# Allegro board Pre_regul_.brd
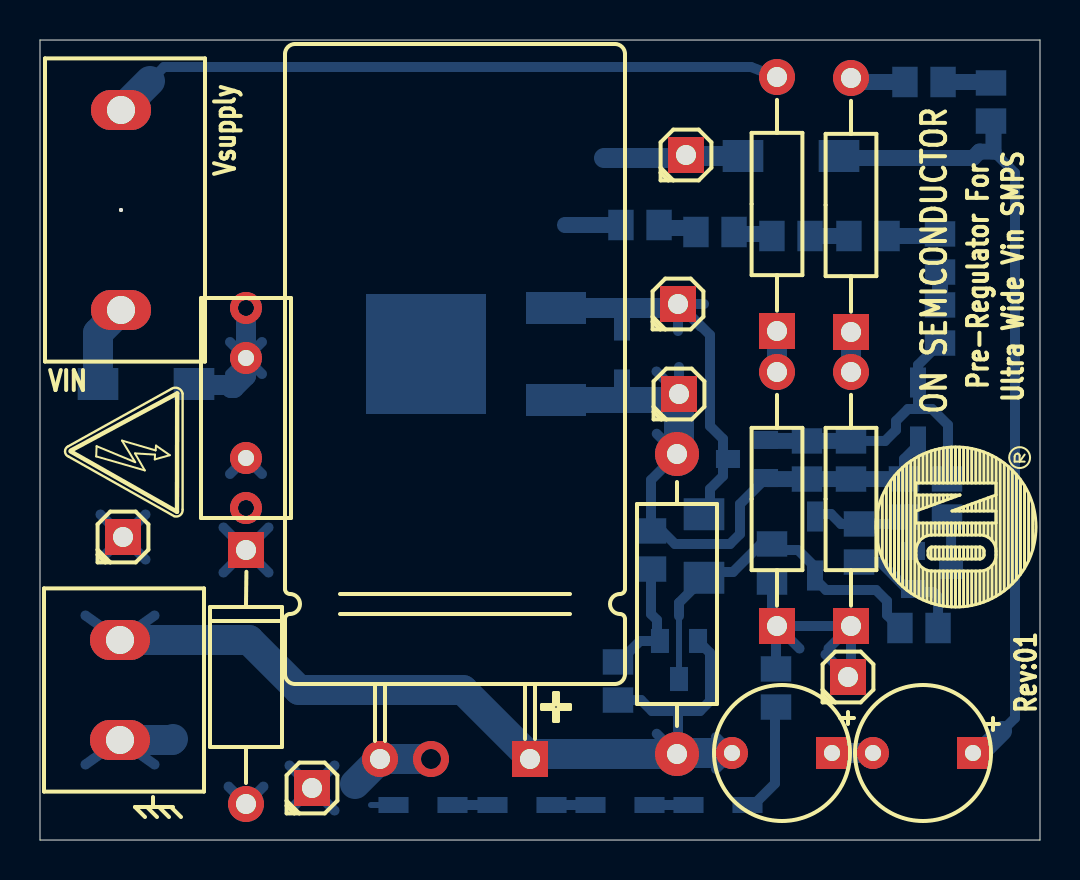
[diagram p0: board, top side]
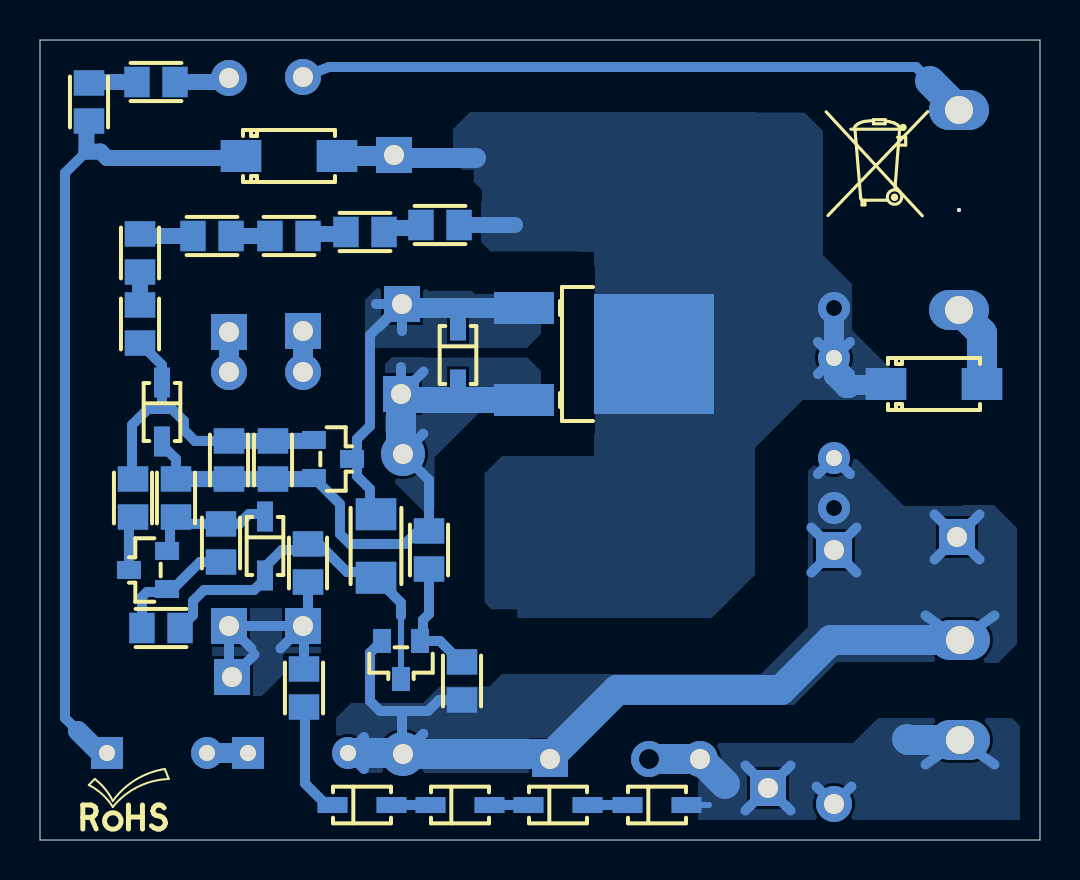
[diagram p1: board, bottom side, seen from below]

Outline 50 x 40 mm; copper layers: TOP, IN1, IN2, BOTTOM. Coordinates in mm from the lower left corner of the outline.
Outline path: 0,40 0,0 50,0 50,40 0,40

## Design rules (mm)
net group 700V: nets N2500670 V IN
net group 200-400V: nets N2499892 N2499948 N2500024 N2500332 N2500480 N2500674 N2500806 N2500814 N2500818 N2500822 N25000601
net group 600V: nets V SUPPLY

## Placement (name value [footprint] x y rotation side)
C1  100pF  [CAPA_DISK_D7-5_P5]  10.3 21.6 270 top
C2  1n  [0805]  38.35 19 90 bottom
C3  22uF 250V  [CAPA_CH_D16XL32_P5]  20.75 4.05 90 top
C4  100n  [0805]  43.2 17.1 90 bottom
C5  1 uF / 450 V  [CAPA_CH_D6-3XL11_P5]  44.15 4.35 180 top
C6  2 x 1 uF / 450 V  [CAPA_CH_D6-3XL11_P5]  37.1 4.35 180 top
CN1  CON3  [BORNIER_3P_5MM]  4.05 34 90 top
CN2  CON2  [BORNIER_2P_5MM]  4 7.5 90 top
D1  MRA4007T3G  [DO214AC_SMA_POL]  5.3 22.8 180 bottom
D2  MMSD4148  [SOD123]  43.9 21.4 270 bottom
D3  MRA4007T3G  [DO214AC_SMA_POL]  37.55 34.2 180 bottom
D4  MMSD4148  [SOD123]  38.75 14.7 270 bottom
DRAIN  TEST POINT  [HE14_1X1]  32.3 34.25 0 top
GATE  TEST POINT  [HE14_1X1]  31.9 26.8 0 top
GND  TEST POINT  [HE14_1X1]  13.6 2.6 0 top
JP1  0R  [1206]  33.2 14.7 90 bottom
NOREF  -  []  0 0 90 top
NOREF#2  -  []  0 40 0 top
NOREF#3  -  []  4.05 36.5 90 top
NOREF#4  -  []  0 40 0 top
NOREF#5  -  []  -181 -35.85 0 top
NOREF#6  -  []  -114.15 -45.45 0 top
NOREF#7  -  []  283.55 -61.75 180 bottom
Q1  NDD02N60Z  [DPAK_TO252]  20.9 24.3 270 bottom
Q2  BC848B  [SOT23]  35.35 19.05 90 bottom
Q3  BC858B  [SOT23]  44.6 13.5 270 bottom
Q4  BC848B  [SOT23]  31.95 9 180 bottom
R1  0.15 R 2W  [WP2S_15MM]  31.85 11.8 270 top
R2  10k  [0805]  40.55 19 270 bottom
R3  1k  [0805]  30.55 14.5 90 bottom
R4  NC  [0805]  28.9 7.95 90 bottom
R5  150K  [0805]  30 30.75 0 bottom
R6  150K  [0805]  33.75 30.4 180 bottom
R7  150K  [0805]  37.55 30.2 0 bottom
R8  150K  [0805]  41.4 30.2 180 bottom
R9  150K  [0805]  45 29.35 270 bottom
R10  150K  [0805]  45 25.8 270 bottom
R11  1k  [0805]  45.35 17.1 90 bottom
R12  10k  [0805]  43.95 10.6 0 bottom
R13  10k  [0805]  40.95 14.85 270 bottom
R14  10k  [0805]  36.6 13.85 90 bottom
R15  100K 1/4W  [RC21U_12-5MM]  36.85 31.8 90 top
R16  100K 1/4W  [RC21U_12-5MM]  36.85 17.05 90 top
R17  330K  [0805]  47.55 36.9 270 bottom
R18  330K  [0805]  44.2 37.9 0 bottom
R19  680K 1/4W  [RC21U_12-5MM]  40.55 31.75 90 top
R20  680K 1/4W  [RC21U_12-5MM]  40.55 17.05 90 top
R21  10k  [0805]  36.8 7.6 90 bottom
SOURCE  TEST POINT  [HE14_1X1]  31.95 22.3 0 top
VOUT  TEST POINT  [HE14_1X1]  4.15 15.15 0 top
VREF  TEST POINT  [HE14_1X1]  40.4 8.15 0 top
ZD1  10V  [SOD123]  29.1 24.25 270 bottom
ZD2  250 V  [DO15_12-5MM]  10.3 8.15 270 top
ZD3  82 V  [SOD123]  33.9 1.75 180 bottom
ZD4  82 V  [SOD123]  29 1.75 180 bottom
ZD5  110 V  [SOD123]  24.1 1.75 180 bottom
ZD6  110 V  [SOD123]  19.15 1.75 180 bottom

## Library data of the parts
C1 = C.MPP_MEF_Pitch-20mm
C2 C4 = C
C3 C5 C6 = C_elect
CN1 = CON3
CN2 = CON2
D1 D3 = D1N4937_1
D2 D4 = D1N4937_0
DRAIN GATE GND SOURCE VOUT VREF = TEST POINT_0
JP1 = JUMPER1_3
Q1 = ST723/PF_0
Q2 Q4 = BC848A
Q3 = BC858A
R1-R21 = R
ZD1-ZD6 = zener_0

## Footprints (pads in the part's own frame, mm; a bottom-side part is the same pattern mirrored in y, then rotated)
0805
  rect 1.27x1.524 smd: 1(-0.953,0) 2(0.953,0)
1206
  rect 1.6x2.03 smd: 1(-1.587,0) 2(1.587,0)
BORNIER_2P_5MM
  oval 2x3 hole 1.4: 1(2.5,0) 2(-2.5,0)
BORNIER_3P_5MM
  round 0.2 hole 1.3 unplated: (-2.5,0)
  oval 2x3 hole 1.4: 1(2.5,0) 3(-7.5,0)
CAPA_CH_D6-3XL11_P5
  round 1.6 hole 0.8: N(2.5,0)
  rect 1.6x1.6 hole 0.8: P(-2.5,0)
CAPA_CH_D16XL32_P5
  round 1.8 hole 1: N(0,3.75)
  rect 1.8x1.8 hole 1: P(0,-3.75)
CAPA_DISK_D7-5_P5
  round 1.6 hole 0.8: 1(-2.5,0) 2(2.5,0)
DO15_12-5MM
  rect 1.8x1.8 hole 1: 1(-6.35,0)
  round 1.8 hole 1: 2(6.35,0)
DO214AC_SMA_POL
  rect 2.03x1.6 smd: 1(2.4,0) 2(-2.4,0)
DPAK_TO252
  rect 1.6x3 smd: 1(-2.3,-4.9) 3(2.3,-4.9)
  rect 6x6 smd: 4(0,1.6)
HE14_1X1
  rect 1.8x1.8 hole 1: 1(0,0)
RC21U_12-5MM
  rect 1.8x1.8 hole 1: 1(-6.35,0)
  round 1.8 hole 1: 2(6.35,0)
SOD123
  rect 1.5x0.8 smd: 1(-1.475,0) 2(1.475,0)
SOT23
  rect 0.9x1.2 smd: 1(0.953,0.953) 2(-0.953,0.953) 3(0,-0.953)
WP2S_15MM
  round 2.2 hole 1: 1(-7.5,0) 2(7.5,0)

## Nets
GND: C3.N(-) CN2.2 GND.1 ZD2.2(ANODE) ZD6.2(ANODE)
V IN: CN1.3 D1.1(A)
V SUPPLY: CN1.1 R15.2
V_OUT: C1.2 C3.P(+) C6.N(-) CN2.1 Q4.2(E) R1.2 R4.1 VOUT.1 ZD2.1(CATHODE)
N2499892: R15.1 R16.2
N2499896: C1.1 D1.2(K) D3.1(A) DRAIN.1 Q1.4(D) R5.1
N2499948: C2.2 D2.1(K) Q2.1(B) R2.1 R10.2 R11.2
N2500020: C2.1 C4.2 D2.2(A) Q1.3(S) Q2.2(E) R1.1 R2.2 R3.2 SOURCE.1 ZD1.2(ANODE)
N2500024: Q3.1(B) R12.2 R13.2
N2500332: C4.1 D4.1(K) Q3.2(E) R13.1
N2500376: GATE.1 JP1.2 Q1.1(G) Q2.3(C) ZD1.1(CATHODE)
N2500480: Q4.1(B) R3.1 R4.2
N2500568: R14.1 R16.1 R20.1 R21.2 VREF.1
N2500670: C5.P(+) D3.2(K) R17.2
N2500674: C5.N(-) C6.P(+)
N2500806: ZD5.2(ANODE) ZD6.1(CATHODE)
N2500814: R21.1 ZD3.1(CATHODE)
N2500818: ZD3.2(ANODE) ZD4.1(CATHODE)
N2500822: ZD4.2(ANODE) ZD5.1(CATHODE)
N2500826: D4.2(A) JP1.1 Q4.3(C) R12.1 R14.2
N2507925: R19.1 R20.2
N2523480: R8.1 R9.1
N2523484: R7.2 R8.2
N2523488: R6.1 R7.1
N2524728: R18.1 R19.2
N25000601: Q3.3(C) R11.1
N25006620: R5.2 R6.2
N25006901: R17.1 R18.2
N25232911: R9.2 R10.1

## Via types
v1: diameter 1.6, hole 0.8, TOP to BOTTOM, 2 vias
v2: diameter 1.8, hole 1, TOP to BOTTOM, 1 via

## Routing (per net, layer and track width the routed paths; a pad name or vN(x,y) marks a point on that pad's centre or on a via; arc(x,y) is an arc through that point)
GND: length 21.2
  BOTTOM w0.3: 17.68,1.75 16.55,1.75
  BOTTOM w0.5: 9.43,2.67 ZD2.2 11.17,2.67 ; 12.47,3.73 GND.1 ; GND.1 14.73,3.73 ; GND.1 12.47,1.47 ; GND.1 14.73,1.47 ; 5.73,3.77 CN2.2 2.27,3.77
  BOTTOM w1.5: 15.75,2.8 C3.N v2(19.55,4.05) ; CN2.2 6.6,5 6.65,5.05
V IN: length 4.2
  BOTTOM w1.5: D1.1 2.9,25.35 CN1.3
V SUPPLY: length 33.8
  BOTTOM w0.5: 5.5,37.95 6.2,38.65 35.55,38.65 R15.2
  BOTTOM w1.5: CN1.1 5.5,37.95
V_OUT: length 68.1
  BOTTOM w0.5: VOUT.1 5.28,14.02 ; VOUT.1 3.02,14.02 ; VOUT.1 5.28,16.28 ; VOUT.1 3.02,16.28 ; 31.9,4.35 31.9,6.45 ; 31.9,6.45 33,6.45 33.5,6.95 33.5,9.36 Q4.2 ; 31.9,6.45 30.6,6.45 30.05,7 R4.1 ; ZD2.1 11.43,15.63 ; ZD2.1 9.17,13.37 ; ZD2.1 11.43,13.37 ; ZD2.1 9.17,15.63 ; 30.84,5.31 R1.2 ; 9.5,18.3 C1.2 11.1,18.3 ; 23.37,5.18 C3.P ; 33.8,5.15 C6.N 33.8,3.55 ; 2.27,11.23 CN2.1 5.73,11.23
  BOTTOM w1.5: C6.N 31.9,4.35 R1.2 24.75,4.3 C3.P 24.5,4.15 21.15,7.5 12.95,7.5 10.45,10 CN2.1
  vias: v1(10.3,16.6)
N2499892: length 2.1
  BOTTOM w1: R15.1 R16.2
N2499896: length 20.9
  BOTTOM w0.5: C1.1 11.1,23.3 ; C1.1 11.1,24.9 ; C1.1 9.5,23.3 ; C1.1 9.5,24.9 ; 26.15,30.85 26.25,30.75
  BOTTOM w0.8: 26.25,30.75 R5.1
  BOTTOM w1: D1.2 7.65,22.75 9.4,22.75 9.55,22.6 9.7,22.6 10.3,23.2 C1.1 v1(10.3,26.6) ; 28.2,34.1 32.15,34.1 DRAIN.1 32.35,34.2 D3.1
N2499948: length 16.8
  BOTTOM w0.5: 43.9,21.55 D2.1 43.9,23.75 R10.2 ; 43.9,21.55 43.4,21.55 42.8,20.95 42.8,20.5 42.25,19.95 R2.1 ; 43.9,21.55 44.6,21.55 45.4,20.75 45.4,18.1 R11.2
  BOTTOM w0.8: Q2.1 36.35,19.95 C2.2 R2.1
N2500020: length 36.2
  BOTTOM w0.3: ZD1.2 29.1,22
  BOTTOM w0.5: 31.95,23.65 SOURCE.1 30.82,23.43 ; Q2.2 35,16.8 35,15.3 34.5,14.8 31.75,14.8 31.1,15.45 R3.2 30.55,18 R1.1 30.84,20.31 ; C4.2 43.2,19.05 43.9,19.75 D2.2
  BOTTOM w0.8: C4.2 43.2,18.05 R2.2 C2.1 36.35,18.05 Q2.2
  BOTTOM w1.3: Q1.3 31.65,22 SOURCE.1
  BOTTOM w1.5: R1.1 31.95,19.4 SOURCE.1
N2500024: length 6.2
  BOTTOM w0.5: R12.2 44.9,12.15 44.65,12.4 43.8,12.4 Q3.1 43.35,12.55 42,13.9 R13.2
N2500332: length 6.7
  BOTTOM w0.5: Q3.2 43.5,14.6 43.5,15.85 C4.1 42.85,15.8 R13.1 40.05,15.8 39.55,16.3 38.88,16.3 D4.1
N2500376: length 23.6
  BOTTOM w0.3: 34.15,19.05 Q2.3
  BOTTOM w0.5: 29.1,25.52 ZD1.1 29.1,26.5 ; JP1.2 33.5,16.59 33.5,17.55 34.15,18.2 34.15,20.05 33.5,20.7 33.5,25.25 31.95,26.8 ; GATE.1 33.03,25.67 ; GATE.1 31.9,25.45 ; GATE.1 31.95,26.8 ; 31.95,26.8 33.2,26.8
  BOTTOM w1: 29,26.6 Q1.1 ; 29,26.6 29.1,26.5 ; 29,26.6 31.7,26.6 GATE.1
N2500480: length 6.3
  BOTTOM w0.5: R3.1 30.55,11.3 30.85,11 30.85,10.1 Q4.1 31,9.95 30,9.95 28.95,8.9 R4.2
N2500568: length 15.6
  BOTTOM w0.5: R21.2 36.8,10.65 R16.1 ; R20.1 40.55,8.3 VREF.1 39.27,9.28 ; R20.1 R16.1 ; R20.1 39.42,9.57 ; R16.1 37.98,9.57 ; R16.1 36.6,10.95 R14.1
N2500670: length 41.1
  BOTTOM w0.5: 47.68,34.42 48.75,33.35 48.75,6.1 48.1,5.45
  BOTTOM w0.8: R17.2 47.68,35.82 47.68,34.42 46.97,34.42 46.65,34.1 40.05,34.1 D3.2
  BOTTOM w1: 48.1,5.45 47,4.35 C5.P
N2500674: length 2
  BOTTOM w1: C5.N C6.P
N2500806: length 2
  BOTTOM w0.5: ZD5.2 ZD6.1
N2500814: length 5.7
  BOTTOM w0.3: ZD3.1 35.67,1.75
  BOTTOM w0.5: 35.67,1.75 36.75,2.83 36.75,6.6 R21.1
N2500818: length 1.9
  BOTTOM w0.3: ZD4.1 30.88,1.75
  BOTTOM w0.5: 30.88,1.75 ZD3.2
N2500822: length 1.9
  BOTTOM w0.5: ZD5.1 ZD4.2
N2500826: length 18.6
  BOTTOM w0.3: 31.95,11.2 Q4.3
  BOTTOM w0.5: 31.95,11.2 31.95,11.86 JP1.1 33.49,13.4 34.65,13.4 36.05,14.8 R14.2 36.9,14.5 37.9,14.5 38.75,13.65 D4.2 38.75,13.05 39.3,12.5 41.8,12.5 42.35,11.95 42.35,11.25 R12.1
N2507925: length 2.1
  BOTTOM w0.3: R20.2 40.55,23.3
  BOTTOM w1: R19.1 R20.2
N2523480: length 2.7
  BOTTOM w0.8: R8.1 44.9,30.2 R9.1
N2523484: length 1.9
  BOTTOM w0.8: R7.2 R8.2
N2523488: length 2
  BOTTOM w0.8: R6.1 34.8,30.3 36.5,30.3 R7.1
N2524728: length 2.8
  BOTTOM w0.8: R18.1 40.75,37.9 R19.2
N25000601: length 2.7
  BOTTOM w0.5: R11.1 45.55,15.95 Q3.3
N25006620: length 2
  BOTTOM w0.8: R6.2 32.6,30.6 31.1,30.6 R5.2
N25006901: length 2.4
  BOTTOM w0.8: R18.2 47.5,37.9 R17.1
N25232911: length 1.6
  BOTTOM w0.8: R9.2 R10.1

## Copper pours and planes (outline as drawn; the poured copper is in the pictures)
GND on BOTTOM: 1,1 1,5.7 1.4,6.1 8.1,6.1 9.35,4.85 17.2,4.85 17.65,4.4 17.65,3.45 17.1,2.9 17.1,1
V_OUT on BOTTOM: 3.6,8.9 10.15,8.9 12.3,6.75 20.85,6.75 24.25,3.35 34.35,3.35 35.2,4.2 35.2,6.1 34.45,6.85 30.85,6.85 30.02,7.67 27.52,7.67 26.9,8.3 13.95,8.3 11.6,10.65 11.6,18.45 10.9,19.15 9.25,19.15 6.8,16.7 3.9,16.7 3.85,16.75 2.3,16.75 1.15,15.6 1.15,9.8 2.1,8.85 3.55,8.85
N2499896 on BOTTOM: 14.25,19.6 14.25,13.25 16.4,11.1 26.25,11.1 26.62,11.47 27.38,11.47 27.77,11.88 27.77,18.32 26.88,19.23 23.35,19.23 22.25,20.32 22.25,28.68 23,29.43 27.48,29.43 27.95,29.9 27.95,31.9 27.9,31.95 27.9,32.5 29.35,33.95 29.35,35.55 28.3,36.6 14.35,36.6 14.12,36.38 11.78,36.38 10.85,35.45 10.85,29.25 9.4,27.8 9.4,25.5 7.2,23.3 7.2,22.45 7.65,22 11.85,22
N2500020 on BOTTOM: 27.95,21.45 30.27,19.12 30.27,16.57 30.55,16.3 30.7,16.3 32.75,18.35 32.75,23.8 32.4,24.15 30.9,24.15 30.88,24.12 25.62,24.12 24.95,23.45 24.95,22.65 24.65,22.65 24.55,22.55 24.55,21.9 25.05,21.4 25.1,21.45
N2500376 on BOTTOM: 28.25,27.3 28.4,27.45 30.55,27.45 30.8,27.7 33.05,27.7 33.75,27 33.75,25 33.35,24.6 25.65,24.6 24.95,25.3 24.95,27.1 25.15,27.3
N2500568 on BOTTOM: 36,11.6 41.35,11.6 41.4,11.55 41.4,7.3 41.3,7.2 38.9,7.2 37.85,8.25 37.85,9.25 37.75,9.35 35.95,9.35 35.95,11.55

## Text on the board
BOTTOM: BOT 1/1
Ref Des/Silkscreen Bottom: SILK_BOT
User.Comments: VE_BOT | VE_TOP
TOP: TOP 2/2 | W02/2013
Ref Des/Assembly Top: VSUPPLY | VOUT | GND | VIN
Ref Des/Silkscreen Top: VIN | Vsupply | Pre-Regulator For | Ultra Wide Vin SMPS | Rev:01 | SILK_TOP | ON SEMICONDUCTOR
IN1: IN1 3/4
IN2: IN2 2/4
DIMENSION: Ultra Wide Vin SMPS | Ech :3
BODY_CENTER: Ultra Wide Vin SMPS | ECH : 3
User.9: CHEMICAL NiAu | 35um(1oz) | THICKNESS | MATERIAL | STACKUP | FINISH | SILKSCREEN | MINIMAL GAP | MINIMAL SLIVER | BOARD THICKNESS | SOLDER MASK | COPPER THICKNESS | MARKED ON BOTTOM SOLDERMASK | ALL BOARD ELECTRICALLY TESTED | MANUFACTURE 'S LOGO & DATECODE | COMPLIANT RoHS DIRECTIVE 2011/65/UE | SF /1LAYER | WHITE TOP&BOT | FR4 IMPROVED (low CTE) | GREEN BOT | 300um /12mils | 1.6mm /63mils | Ultra Wide Vin SMPS | SPEC:
User.10: EVB PreRegulator 1302-0682 w08/2013
User.11: FIGURE | SIZE | 0.8 | 1.0 | 1.4 | 1.3 | DRILL CHART: TOP to BOTTOM | ALL UNITS ARE IN MILLIMETERS | PLATED | QTY | 8 | 21 | 4 | 1
